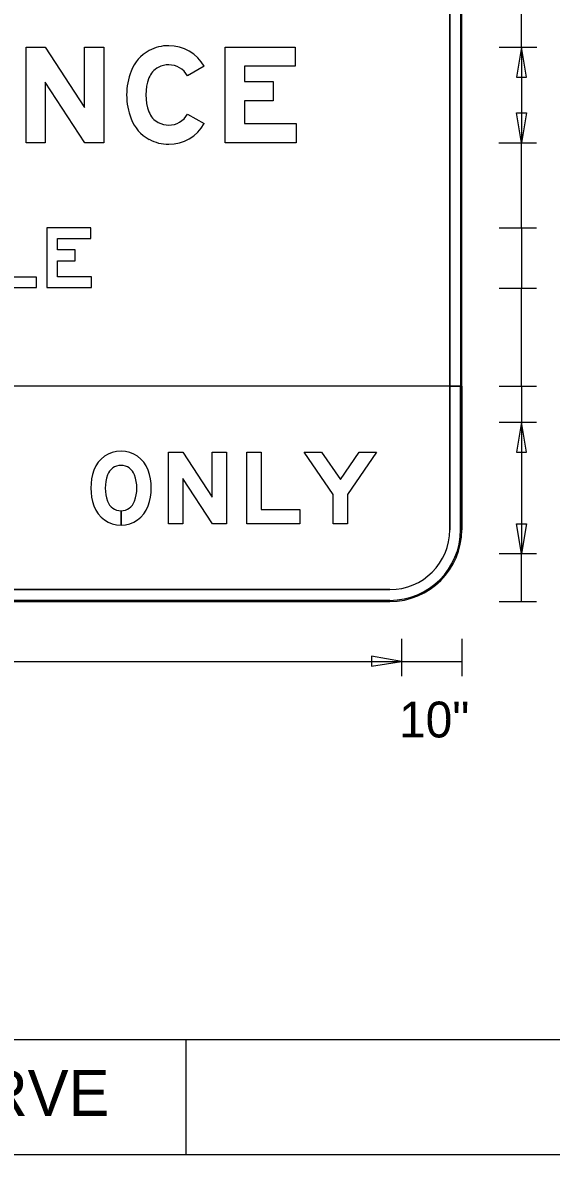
# Model space of a CAD drawing. Extents: x 119523 to 121850, y -23542 to -19972.
# Drawn here: x 120372.9 to 120461.3, y -22408.6 to -22219.3 of the extents above; entities that cross this region are included whole.
import ezdxf

# ---------------------------------------------------------------- set-up
doc = ezdxf.new("R2010")
doc.units = 0
for name, color, linetype in [('GSBWFill', 7, 'Continuous'), ('GSColorFill', 7, 'Continuous'), ('GSDims', 7, 'Continuous'), ('GSOutline', 7, 'Continuous'), ('SheetLinesMisc2_dp', 7, 'Continuous'), ('TextMinor', 7, 'Continuous')]:
    doc.layers.add(name, color=color, linetype=linetype)

msp = doc.modelspace()

# ---------------------------------------------------------------- linework, layer by layer
at = {"layer": 'GSBWFill'}
for p, q in [((120444.27, -22154.11), (120444.27, -22304.11)), ((120446.27, -22304.11), (120446.27, -22154.11)), ((120446.27, -22280.1), (120266.27, -22280.1)), ((120444.27, -22282.1), (120444.27, -22280.1)), ((120444.27, -22280.1), (120446.27, -22280.1)), ((120446.27, -22280.1), (120446.27, -22304.11)), ((120446.27, -22304.11), (120446.27, -22280.1)), ((120444.27, -22304.11), (120444.27, -22282.1)), ((120389.33, -22300.92), (120389.33, -22303.32)), ((120389.34, -22303.32), (120389.34, -22300.92)), ((120278.27, -22314.11), (120434.27, -22314.11)), ((120434.27, -22314.11), (120278.29, -22314.11)), ((120434.27, -22316.11), (120278.27, -22316.11)), ((120278.27, -22316.11), (120434.27, -22316.11)), ((120278.29, -22316.11), (120434.27, -22316.11))]:
    msp.add_line(p, q, dxfattribs=at)
for points in [[(120373.47, -22223.4), (120376.67, -22223.4), (120383.23, -22233.48), (120383.23, -22223.4), (120386.43, -22223.4), (120386.43, -22239.4), (120383.27, -22239.4), (120376.67, -22229.27), (120376.67, -22239.4), (120373.47, -22239.4)], [(120418.43, -22223.4), (120418.43, -22226.6), (120409.95, -22226.6), (120409.95, -22229.16), (120414.75, -22229.16), (120414.75, -22232.36), (120409.95, -22232.36), (120409.95, -22236.2), (120418.59, -22236.2), (120418.59, -22239.4), (120406.75, -22239.4), (120406.75, -22223.4)], [(120375.21, -22263.6), (120375.21, -22261.85), (120369.51, -22261.85), (120369.51, -22253.6), (120367.71, -22253.6), (120367.71, -22263.6)], [(120384.41, -22261.8), (120378.71, -22261.8), (120378.71, -22259.11), (120381.66, -22259.11), (120381.66, -22257.31), (120378.71, -22257.31), (120378.71, -22255.4), (120384.26, -22255.4), (120384.26, -22253.6), (120376.91, -22253.6), (120376.91, -22263.6), (120384.41, -22263.6)], [(120397.25, -22291.11), (120399.65, -22291.11), (120404.57, -22298.66), (120404.57, -22291.11), (120406.97, -22291.11), (120406.97, -22303.11), (120404.6, -22303.11), (120399.65, -22295.51), (120399.65, -22303.11), (120397.25, -22303.11)], [(120412.73, -22300.71), (120419.21, -22300.71), (120419.21, -22303.11), (120410.33, -22303.11), (120410.33, -22291.11), (120412.73, -22291.11)], [(120427.19, -22303.11), (120424.79, -22303.11), (120424.79, -22298.19), (120419.93, -22291.11), (120422.85, -22291.11), (120425.99, -22295.69), (120429.14, -22291.11), (120432.05, -22291.11), (120427.19, -22298.19)]]:
    msp.add_lwpolyline(points, close=True, dxfattribs=at)
for points in [[(120403.23, -22226.61), (120400.45, -22228.18)], [(120400.45, -22234.62), (120403.23, -22236.2)]]:
    msp.add_lwpolyline(points, dxfattribs=at)
for centre, radius, start, end in [((120389.33, -22295.74), 4.8, 19.6063, 160.3937), ((120393.23, -22297.13), 8.94, 160.3938, 199.6063), ((120389.33, -22295.74), 2.4, 19.6063, 160.3937), ((120385.44, -22297.13), 8.94, 340.3938, 19.6063), ((120393.23, -22297.13), 6.54, 160.3937, 199.6063), ((120385.44, -22297.13), 6.54, 340.3937, 19.6062), ((120389.33, -22298.52), 4.8, 199.6063, 270), ((120389.33, -22298.52), 2.4, 199.6063, 270), ((120389.33, -22298.52), 2.4, 270.0143, 340.3938), ((120389.33, -22298.52), 4.8, 270.0072, 340.3937), ((120434.27, -22304.11), 12, 270, 0), ((120434.27, -22304.11), 10, 270, 0), ((120434.27, -22304.11), 12, 270, 0), ((120434.27, -22304.11), 10, 270, 0), ((120434.27, -22304.11), 12, 270, 0)]:
    msp.add_arc(centre, radius, start, end, dxfattribs=at)
for centre, major_axis, start_param, end_param in [((120397.14, -22229.75), (0, 6.56), 0.495249, 1.205818), ((120397.31, -22230.07), (0, 6.91), 0, 0.495249), ((120397.31, -22229.97), (0, 6.81), 5.228016, 6.283185), ((120397.31, -22230.07), (0, 3.71), 0, 0.495249), ((120397.31, -22229.97), (0, 3.61), 5.228016, 6.283185), ((120401.45, -22231.4), (0, 11.18), 1.205818, 1.935775), ((120401.45, -22231.4), (0, 7.98), 1.205818, 1.935775), ((120397.14, -22229.75), (0, 3.36), 0.495249, 1.205818), ((120397.14, -22233.05), (0, 6.56), 1.935775, 2.646344), ((120397.14, -22233.05), (0, 3.36), 1.935775, 2.646344), ((120397.31, -22232.74), (0, 3.71), 2.646344, 3.141593), ((120397.31, -22232.84), (0, 3.61), 3.141593, 4.196762), ((120397.31, -22232.84), (0, 6.81), 3.141593, 4.196762), ((120397.31, -22232.74), (0, 6.91), 2.646344, 3.141593)]:
    msp.add_ellipse(centre, major_axis=major_axis, ratio=0.999994, start_param=start_param, end_param=end_param, dxfattribs=at)
at = {"layer": 'GSColorFill'}
for p, q in [((120444.27, -22154.11), (120444.27, -22304.11)), ((120446.07, -22154.11), (120446.07, -22304.11)), ((120446.27, -22304.11), (120446.27, -22154.11)), ((120446.27, -22304.11), (120446.27, -22154.11)), ((120446.27, -22304.11), (120446.27, -22154.11)), ((120446.27, -22280.1), (120266.27, -22280.1)), ((120444.27, -22282.1), (120444.27, -22280.1)), ((120444.27, -22280.1), (120446.27, -22280.1)), ((120446.07, -22280.3), (120446.07, -22280.1)), ((120446.07, -22280.1), (120446.27, -22280.1)), ((120446.07, -22304.11), (120446.07, -22280.3)), ((120446.27, -22304.11), (120446.27, -22280.1)), ((120446.27, -22280.1), (120446.27, -22304.11)), ((120446.27, -22280.1), (120446.27, -22304.11)), ((120444.27, -22304.11), (120444.27, -22282.1)), ((120389.33, -22300.92), (120389.33, -22303.32)), ((120389.34, -22303.32), (120389.34, -22300.92)), ((120278.27, -22314.11), (120434.27, -22314.11)), ((120434.27, -22314.11), (120278.29, -22314.11)), ((120278.27, -22315.91), (120434.27, -22315.91)), ((120278.27, -22316.11), (120434.27, -22316.11)), ((120278.27, -22316.11), (120434.27, -22316.11)), ((120434.27, -22316.11), (120278.27, -22316.11)), ((120434.27, -22316.11), (120278.27, -22316.11)), ((120434.27, -22315.91), (120278.28, -22315.91)), ((120278.28, -22316.11), (120434.27, -22316.11)), ((120278.29, -22316.11), (120434.27, -22316.11))]:
    msp.add_line(p, q, dxfattribs=at)
for points in [[(120373.47, -22223.4), (120376.67, -22223.4), (120383.23, -22233.48), (120383.23, -22223.4), (120386.43, -22223.4), (120386.43, -22239.4), (120383.27, -22239.4), (120376.67, -22229.27), (120376.67, -22239.4), (120373.47, -22239.4)], [(120418.43, -22223.4), (120418.43, -22226.6), (120409.95, -22226.6), (120409.95, -22229.16), (120414.75, -22229.16), (120414.75, -22232.36), (120409.95, -22232.36), (120409.95, -22236.2), (120418.59, -22236.2), (120418.59, -22239.4), (120406.75, -22239.4), (120406.75, -22223.4)], [(120375.21, -22263.6), (120375.21, -22261.85), (120369.51, -22261.85), (120369.51, -22253.6), (120367.71, -22253.6), (120367.71, -22263.6)], [(120384.41, -22261.8), (120378.71, -22261.8), (120378.71, -22259.11), (120381.66, -22259.11), (120381.66, -22257.31), (120378.71, -22257.31), (120378.71, -22255.4), (120384.26, -22255.4), (120384.26, -22253.6), (120376.91, -22253.6), (120376.91, -22263.6), (120384.41, -22263.6)], [(120397.25, -22291.11), (120399.65, -22291.11), (120404.57, -22298.66), (120404.57, -22291.11), (120406.97, -22291.11), (120406.97, -22303.11), (120404.6, -22303.11), (120399.65, -22295.51), (120399.65, -22303.11), (120397.25, -22303.11)], [(120412.73, -22300.71), (120419.21, -22300.71), (120419.21, -22303.11), (120410.33, -22303.11), (120410.33, -22291.11), (120412.73, -22291.11)], [(120427.19, -22303.11), (120424.79, -22303.11), (120424.79, -22298.19), (120419.93, -22291.11), (120422.85, -22291.11), (120425.99, -22295.69), (120429.14, -22291.11), (120432.05, -22291.11), (120427.19, -22298.19)]]:
    msp.add_lwpolyline(points, close=True, dxfattribs=at)
for points in [[(120403.23, -22226.61), (120400.45, -22228.18)], [(120400.45, -22234.62), (120403.23, -22236.2)]]:
    msp.add_lwpolyline(points, dxfattribs=at)
for centre, radius, start, end in [((120389.33, -22295.74), 4.8, 19.6063, 160.3937), ((120393.23, -22297.13), 8.94, 160.3938, 199.6063), ((120389.33, -22295.74), 2.4, 19.6063, 160.3937), ((120385.44, -22297.13), 8.94, 340.3938, 19.6063), ((120393.23, -22297.13), 6.54, 160.3937, 199.6063), ((120385.44, -22297.13), 6.54, 340.3937, 19.6062), ((120389.33, -22298.52), 4.8, 199.6063, 270), ((120389.33, -22298.52), 2.4, 199.6063, 270), ((120389.33, -22298.52), 2.4, 270.0143, 340.3938), ((120389.33, -22298.52), 4.8, 270.0072, 340.3937), ((120434.27, -22304.11), 12, 270, 0), ((120434.27, -22304.11), 12, 270, 0), ((120434.27, -22304.11), 10, 270, 0), ((120434.27, -22304.11), 12, 270, 0), ((120434.27, -22304.11), 11.8, 270, 0), ((120434.27, -22304.11), 12, 270, 0), ((120434.27, -22304.11), 12, 270, 0), ((120434.27, -22304.11), 10, 270, 0), ((120434.27, -22304.11), 12, 270, 0), ((120434.27, -22304.11), 11.8, 270, 0)]:
    msp.add_arc(centre, radius, start, end, dxfattribs=at)
for centre, major_axis, start_param, end_param in [((120397.14, -22229.75), (0, 6.56), 0.495249, 1.205818), ((120397.31, -22230.07), (0, 6.91), 0, 0.495249), ((120397.31, -22229.97), (0, 6.81), 5.228016, 6.283185), ((120397.31, -22230.07), (0, 3.71), 0, 0.495249), ((120397.31, -22229.97), (0, 3.61), 5.228016, 6.283185), ((120401.45, -22231.4), (0, 11.18), 1.205818, 1.935775), ((120401.45, -22231.4), (0, 7.98), 1.205818, 1.935775), ((120397.14, -22229.75), (0, 3.36), 0.495249, 1.205818), ((120397.14, -22233.05), (0, 6.56), 1.935775, 2.646344), ((120397.14, -22233.05), (0, 3.36), 1.935775, 2.646344), ((120397.31, -22232.74), (0, 3.71), 2.646344, 3.141593), ((120397.31, -22232.84), (0, 3.61), 3.141593, 4.196762), ((120397.31, -22232.84), (0, 6.81), 3.141593, 4.196762), ((120397.31, -22232.74), (0, 6.91), 2.646344, 3.141593)]:
    msp.add_ellipse(centre, major_axis=major_axis, ratio=0.999994, start_param=start_param, end_param=end_param, dxfattribs=at)
at = {"layer": 'GSDims'}
for p, q in [((120456.27, -22223.4), (120456.27, -22211.4)), ((120452.55, -22223.4), (120458.8, -22223.4)), ((120456.27, -22223.4), (120456.27, -22239.51)), ((120452.5, -22239.4), (120458.75, -22239.4)), ((120456.27, -22253.71), (120456.27, -22239.51)), ((120452.52, -22253.6), (120458.77, -22253.6)), ((120456.27, -22253.71), (120456.27, -22263.71)), ((120452.52, -22263.71), (120458.77, -22263.71)), ((120452.52, -22263.71), (120458.77, -22263.71)), ((120456.27, -22280.1), (120456.27, -22263.71)), ((120452.52, -22280.1), (120458.77, -22280.1)), ((120456.27, -22280.1), (120456.27, -22286.12)), ((120452.52, -22286.12), (120458.77, -22286.12)), ((120456.27, -22286.12), (120456.27, -22308.09)), ((120452.52, -22308.09), (120458.77, -22308.09)), ((120452.52, -22308.09), (120458.77, -22308.09)), ((120456.27, -22316.11), (120456.27, -22308.09)), ((120452.52, -22316.11), (120458.77, -22316.11)), ((120452.52, -22316.11), (120458.77, -22316.11)), ((120436.22, -22322.36), (120436.22, -22328.61)), ((120436.22, -22322.36), (120436.22, -22328.61)), ((120446.27, -22322.36), (120446.27, -22328.61)), ((120276.27, -22326.11), (120436.22, -22326.11)), ((120436.22, -22326.11), (120446.27, -22326.11))]:
    msp.add_line(p, q, dxfattribs=at)
for points in [[(120456.27, -22223.4), (120455.44, -22228.4), (120457.11, -22228.4)], [(120456.27, -22239.4), (120455.44, -22234.4), (120457.11, -22234.4)], [(120456.27, -22286.12), (120455.44, -22291.12), (120457.11, -22291.12)], [(120456.27, -22308.09), (120455.44, -22303.09), (120457.11, -22303.09)], [(120436.22, -22326.11), (120431.22, -22325.27), (120431.22, -22326.94)]]:
    msp.add_lwpolyline(points, close=True, dxfattribs=at)
at = {"layer": 'GSOutline'}
for p, q in [((120444.27, -22304.11), (120444.27, -22154.11)), ((120446.27, -22304.11), (120446.27, -22154.11)), ((120446.27, -22280.1), (120266.27, -22280.1)), ((120444.27, -22282.1), (120444.27, -22280.1)), ((120444.27, -22280.1), (120446.27, -22280.1)), ((120446.27, -22280.1), (120446.27, -22304.11)), ((120446.27, -22304.11), (120446.27, -22280.1)), ((120444.27, -22304.11), (120444.27, -22282.1)), ((120278.27, -22314.11), (120434.27, -22314.11)), ((120278.27, -22314.11), (120434.27, -22314.11)), ((120278.27, -22316.11), (120434.27, -22316.11)), ((120434.27, -22316.11), (120278.27, -22316.11)), ((120278.27, -22316.11), (120434.27, -22316.11))]:
    msp.add_line(p, q, dxfattribs=at)
for points in [[(120373.47, -22223.4), (120376.67, -22223.4), (120383.23, -22233.48), (120383.23, -22223.4), (120386.43, -22223.4), (120386.43, -22239.4), (120383.27, -22239.4), (120376.67, -22229.27), (120376.67, -22239.4), (120373.47, -22239.4)], [(120418.43, -22223.4), (120418.43, -22226.6), (120409.95, -22226.6), (120409.95, -22229.16), (120414.75, -22229.16), (120414.75, -22232.36), (120409.95, -22232.36), (120409.95, -22236.2), (120418.59, -22236.2), (120418.59, -22239.4), (120406.75, -22239.4), (120406.75, -22223.4)], [(120375.21, -22263.6), (120375.21, -22261.85), (120369.51, -22261.85), (120369.51, -22253.6), (120367.71, -22253.6), (120367.71, -22263.6)], [(120384.41, -22261.8), (120378.71, -22261.8), (120378.71, -22259.11), (120381.66, -22259.11), (120381.66, -22257.31), (120378.71, -22257.31), (120378.71, -22255.4), (120384.26, -22255.4), (120384.26, -22253.6), (120376.91, -22253.6), (120376.91, -22263.6), (120384.41, -22263.6)], [(120397.25, -22291.11), (120399.65, -22291.11), (120404.57, -22298.66), (120404.57, -22291.11), (120406.97, -22291.11), (120406.97, -22303.11), (120404.6, -22303.11), (120399.65, -22295.51), (120399.65, -22303.11), (120397.25, -22303.11)], [(120412.73, -22300.71), (120419.21, -22300.71), (120419.21, -22303.11), (120410.33, -22303.11), (120410.33, -22291.11), (120412.73, -22291.11)], [(120427.19, -22303.11), (120424.79, -22303.11), (120424.79, -22298.19), (120419.93, -22291.11), (120422.85, -22291.11), (120425.99, -22295.69), (120429.14, -22291.11), (120432.05, -22291.11), (120427.19, -22298.19)]]:
    msp.add_lwpolyline(points, close=True, dxfattribs=at)
for points in [[(120403.23, -22226.61), (120400.45, -22228.18)], [(120400.45, -22234.62), (120403.23, -22236.2)]]:
    msp.add_lwpolyline(points, dxfattribs=at)
for centre, radius, start, end in [((120389.33, -22295.74), 4.8, 19.6063, 160.3937), ((120393.23, -22297.13), 8.94, 160.3937, 199.6063), ((120389.33, -22295.74), 2.4, 19.6063, 160.3937), ((120385.44, -22297.13), 8.94, 340.3937, 19.6062), ((120393.23, -22297.13), 6.54, 160.3937, 199.6063), ((120385.44, -22297.13), 6.54, 340.3937, 19.6062), ((120389.33, -22298.52), 4.8, 199.6063, 340.3938), ((120389.33, -22298.52), 2.4, 199.6063, 340.3938), ((120434.27, -22304.11), 12, 270, 0), ((120434.27, -22304.11), 10, 270, 0), ((120434.27, -22304.11), 12, 270, 0), ((120434.27, -22304.11), 10, 270, 0), ((120434.27, -22304.11), 12, 270, 0)]:
    msp.add_arc(centre, radius, start, end, dxfattribs=at)
for centre, major_axis, start_param, end_param in [((120397.14, -22229.75), (0, 6.56), 0.495249, 1.205818), ((120397.31, -22230.07), (0, 6.91), 0, 0.495249), ((120397.31, -22229.97), (0, 6.81), 5.228016, 6.283185), ((120397.31, -22230.07), (0, 3.71), 0, 0.495249), ((120397.31, -22229.97), (0, 3.61), 5.228016, 6.283185), ((120401.45, -22231.4), (0, 11.18), 1.205818, 1.935775), ((120401.45, -22231.4), (0, 7.98), 1.205818, 1.935775), ((120397.14, -22229.75), (0, 3.36), 0.495249, 1.205818), ((120397.14, -22233.05), (0, 6.56), 1.935775, 2.646344), ((120397.14, -22233.05), (0, 3.36), 1.935775, 2.646344), ((120397.31, -22232.74), (0, 3.71), 2.646344, 3.141593), ((120397.31, -22232.84), (0, 3.61), 3.141593, 4.196762), ((120397.31, -22232.84), (0, 6.81), 3.141593, 4.196762), ((120397.31, -22232.74), (0, 6.91), 2.646344, 3.141593)]:
    msp.add_ellipse(centre, major_axis=major_axis, ratio=0.999994, start_param=start_param, end_param=end_param, dxfattribs=at)
at = {"layer": 'SheetLinesMisc2_dp'}
for p, q in [((119943.36, -22389.32), (120680.14, -22389.32)), ((120400.17, -22389.32), (120400.17, -22408.55)), ((119943.36, -22408.55), (120680.14, -22408.55))]:
    msp.add_line(p, q, dxfattribs=at)

# ---------------------------------------------------------------- texts
at = {"layer": 'GSDims'}
msp.add_text('10"', height=6, dxfattribs=at).set_placement((120435.78, -22338.84))
at = {"layer": 'TextMinor'}
msp.add_text('PHOTOMETRIC CURVE', height=7.6529, dxfattribs=at).set_placement((120273.1, -22402.11))

doc.saveas('drawing.dxf')
